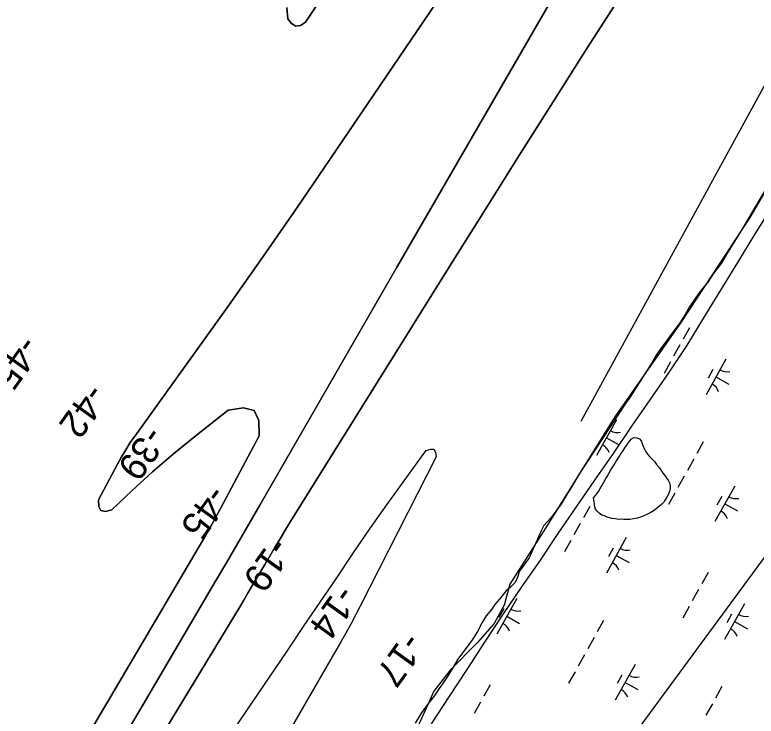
# Model space of a CAD drawing. Extents: x 3923531 to 3943530, y 207391 to 229799.
# Drawn here: x 3936304 to 3937214, y 219001 to 219861 of the extents above; entities that cross this region are included whole.
import ezdxf

# ---------------------------------------------------------------- set-up
doc = ezdxf.new("R2010")
doc.units = 0
for name, color, linetype in [('V-RIVR-EDGE', 7, 'Continuous'), ('V-RIVR-RANG', 7, 'Continuous'), ('V-RRAP-FSHR', 7, 'Continuous'), ('V-TOPO-DPTH', 7, 'Continuous'), ('V-TOPO-MINR', 7, 'Continuous'), ('V-TOPO-SHOR', 7, 'Continuous'), ('V-UTIL-LINE', 7, 'Continuous'), ('V-WETL-SWMP', 7, 'Continuous')]:
    doc.layers.add(name, color=color, linetype=linetype)

msp = doc.modelspace()

# ---------------------------------------------------------------- linework, layer by layer
at = {"layer": 'V-RIVR-EDGE'}
msp.add_lwpolyline([(3937264.42, 219712.49), (3937206.12, 219612.81), (3937121.31, 219483.62), (3937040.42, 219367.91), (3936955.04, 219231.41), (3936911.23, 219162.89), (3936904.49, 219137.05), (3936892.13, 219114.58), (3936871.91, 219090.99), (3936838.21, 219057.29), (3936817.99, 219031.45), (3936801.14, 218994.38), (3936792.15, 218976.4), (3936756.2, 218928.09), (3936705.65, 218856.2), (3936661.83, 218800.03), (3936627.01, 218753.97), (3936580.95, 218730.38), (3936545, 218713.52), (3936503.43, 218703.41), (3936484.84, 218694.49)], dxfattribs=at)
at = {"layer": 'V-RRAP-FSHR'}
msp.add_lwpolyline([(3936815.22, 218991.23), (3936837.11, 219024.71), (3936859.2, 219058.18), (3936880.89, 219091.66), (3936902.79, 219125.14), (3936925.4, 219158.13), (3936948.35, 219191.11), (3936970.67, 219224.9), (3936993.31, 219257.68), (3937015.94, 219290.47), (3937038.58, 219323.26), (3937061.21, 219356.5), (3937083.85, 219388.98), (3937106.48, 219421.96), (3937128.55, 219455.31), (3937149.45, 219489.41), (3937170.35, 219523.52), (3937191.24, 219557.63), (3937212.14, 219591.74), (3937233.37, 219625.84)], dxfattribs=at)
at = {"layer": 'V-TOPO-DPTH'}
for points in [[(3936839.17, 220119.81), (3936660.7, 219852.39), (3936654.31, 219848.4), (3936648.49, 219847.28), (3936643.49, 219850.48), (3936639.04, 219856.55), (3936637.46, 219870.32)], [(3936637.46, 219870.32), (3936639.04, 219856.55), (3936643.49, 219850.48), (3936648.49, 219847.28), (3936654.31, 219848.4), (3936660.7, 219852.39), (3936839.17, 220119.81)], [(3936125.75, 218524.05), (3936538.21, 219223.04), (3936541.92, 219229.42), (3936545.58, 219235.84), (3936549.15, 219242.31), (3936552.66, 219248.8), (3936603.69, 219344.79), (3936603.2, 219363.48), (3936597.58, 219376), (3936584.24, 219379.29), (3936565.77, 219376.43), (3936524.78, 219344.02), (3936498.45, 219322.49), (3936472.62, 219300.4), (3936447.53, 219277.46), (3936422.95, 219253.95), (3936415.13, 219252.06), (3936409.41, 219253.01), (3936406.86, 219258.21), (3936406.43, 219266.24), (3936429.59, 219309.92), (3936434.61, 219318.93), (3936439.87, 219327.78), (3936445.48, 219336.42), (3936451.34, 219344.91), (3936524.41, 219446.28), (3936566.72, 219505.52), (3936608.69, 219564.99), (3936650.15, 219624.83), (3936691.26, 219684.91), (3936943.66, 220057.15)], [(3936943.66, 220057.15), (3936691.26, 219684.91), (3936650.15, 219624.83), (3936608.69, 219564.99), (3936566.72, 219505.52), (3936524.41, 219446.28), (3936451.34, 219344.91), (3936445.48, 219336.42), (3936439.87, 219327.78), (3936434.61, 219318.93), (3936429.59, 219309.92), (3936406.43, 219266.24), (3936406.86, 219258.21), (3936409.41, 219253.01), (3936415.13, 219252.06), (3936422.95, 219253.95), (3936447.53, 219277.46), (3936472.62, 219300.4), (3936498.45, 219322.49), (3936524.78, 219344.02), (3936565.77, 219376.43), (3936584.24, 219379.29), (3936597.58, 219376), (3936603.2, 219363.48), (3936603.69, 219344.79), (3936552.66, 219248.8), (3936549.15, 219242.31), (3936545.58, 219235.84), (3936541.92, 219229.42), (3936538.21, 219223.04), (3936125.75, 218524.05)], [(3937073, 219924.42), (3937006.14, 219819.85), (3936964.69, 219754.77), (3936923.38, 219689.6), (3936882.28, 219624.3), (3936841.33, 219558.9), (3936647.39, 219248.06), (3936641.3, 219238.23), (3936635.26, 219228.36), (3936629.29, 219218.45), (3936623.37, 219208.51), (3936613.73, 219192.2), (3936612.67, 219190.39), (3936610.54, 219186.78), (3936609.48, 219184.98), (3936600.94, 219170.45), (3936595.58, 219161.39), (3936590.21, 219152.34), (3936584.79, 219143.32), (3936579.34, 219134.32), (3936150.31, 218428.2)], [(3936284.04, 218719.6), (3936343.8, 218817.63), (3936402.8, 218916.13), (3936461.3, 219014.93), (3936550.25, 219166.53), (3936563.86, 219189.78), (3936577.43, 219213.05), (3936590.95, 219236.35), (3936604.43, 219259.66), (3936772.41, 219550.86), (3936818.95, 219631.46), (3936865.54, 219712.04), (3936912.19, 219792.58), (3936958.89, 219873.09)], [(3936958.89, 219873.09), (3936912.19, 219792.58), (3936865.54, 219712.04), (3936818.95, 219631.46), (3936772.41, 219550.86), (3936604.43, 219259.66), (3936590.95, 219236.35), (3936577.43, 219213.05), (3936563.86, 219189.78), (3936550.25, 219166.53), (3936461.3, 219014.93), (3936402.8, 218916.13), (3936343.8, 218817.63), (3936284.04, 218719.6)]]:
    msp.add_lwpolyline(points, dxfattribs=at)
at = {"layer": 'V-TOPO-MINR'}
for points in [[(3936998.93, 219362.63), (3937298.09, 219910.54), (3937299.4, 219913.05), (3937300.67, 219915.58), (3937301.85, 219918.14), (3937302.99, 219920.73), (3937323.72, 219970.21), (3937335.15, 219997.57), (3937346.53, 220024.96), (3937357.84, 220052.37), (3937369.1, 220079.8), (3937639.89, 220741.77), (3937648.76, 220763.09), (3937657.81, 220784.33), (3937667.11, 220805.45), (3937676.59, 220826.5), (3937934.29, 221389.52)], [(3936839.17, 220119.81), (3936660.7, 219852.39), (3936654.31, 219848.4), (3936648.49, 219847.28), (3936643.49, 219850.48), (3936639.04, 219856.55), (3936637.46, 219870.32)], [(3936125.75, 218524.05), (3936538.21, 219223.04), (3936541.92, 219229.42), (3936545.58, 219235.84), (3936549.15, 219242.31), (3936552.66, 219248.8), (3936603.69, 219344.79), (3936603.2, 219363.48), (3936597.58, 219376), (3936584.24, 219379.29), (3936565.77, 219376.43), (3936524.78, 219344.02), (3936498.45, 219322.49), (3936472.62, 219300.4), (3936447.53, 219277.46), (3936422.95, 219253.95), (3936415.13, 219252.06), (3936409.41, 219253.01), (3936406.86, 219258.21), (3936406.43, 219266.24), (3936429.59, 219309.92), (3936434.61, 219318.93), (3936439.87, 219327.78), (3936445.48, 219336.42), (3936451.34, 219344.91), (3936524.41, 219446.28), (3936566.72, 219505.52), (3936608.69, 219564.99), (3936650.15, 219624.83), (3936691.26, 219684.91), (3936943.66, 220057.15)], [(3936150.31, 218428.2), (3936579.34, 219134.32), (3936584.79, 219143.32), (3936590.21, 219152.34), (3936595.58, 219161.39), (3936600.94, 219170.45), (3936609.48, 219184.98), (3936610.54, 219186.78), (3936612.67, 219190.39), (3936613.73, 219192.2), (3936623.37, 219208.51), (3936629.29, 219218.45), (3936635.26, 219228.36), (3936641.3, 219238.23), (3936647.39, 219248.06), (3936841.33, 219558.9), (3936882.28, 219624.3), (3936923.38, 219689.6), (3936964.69, 219754.77), (3937006.14, 219819.85), (3937073, 219924.42)], [(3936284.04, 218719.6), (3936343.8, 218817.63), (3936402.8, 218916.13), (3936461.3, 219014.93), (3936550.25, 219166.53), (3936563.86, 219189.78), (3936577.43, 219213.05), (3936590.95, 219236.35), (3936604.43, 219259.66), (3936772.41, 219550.86), (3936818.95, 219631.46), (3936865.54, 219712.04), (3936912.19, 219792.58), (3936958.89, 219873.09)], [(3936290.41, 218549.02), (3936331.52, 218620.72), (3936375.11, 218690.94), (3936420.36, 218760.18), (3936637.9, 219080.65), (3936658.25, 219110.64), (3936678.58, 219140.64), (3936698.9, 219170.65), (3936719.2, 219200.66), (3936739.7, 219230.54), (3936760.47, 219260.23), (3936781.65, 219289.62), (3936803.1, 219318.83), (3936808.89, 219326.58), (3936814.25, 219328.57), (3936818.25, 219328.36), (3936820.21, 219324.87), (3936820.82, 219319.19), (3936727.75, 219135.63), (3936722.04, 219124.6), (3936716.22, 219113.64), (3936710.21, 219102.77), (3936704.09, 219091.97), (3936365.07, 218505.33)]]:
    msp.add_lwpolyline(points, dxfattribs=at)
at = {"layer": 'V-TOPO-SHOR'}
msp.add_lwpolyline([(3937014.24, 219268.6), (3937016.24, 219270.95), (3937018.25, 219273.51), (3937020.25, 219276.25), (3937022.27, 219280.19), (3937024.28, 219283.53), (3937026.7, 219288.06), (3937029.12, 219292.38), (3937030.73, 219294.94), (3937032.95, 219298.68), (3937035.56, 219303), (3937037.78, 219306.74), (3937039.58, 219309.29), (3937041.6, 219313.03), (3937044.01, 219316.37), (3937046.03, 219319.9), (3937047.64, 219322.86), (3937050.04, 219326), (3937052.66, 219329.93), (3937055.07, 219333.46), (3937056.68, 219336.02), (3937058.88, 219338.77), (3937060.88, 219341.12), (3937063.67, 219342.67), (3937067.43, 219342.43), (3937070.58, 219341.02), (3937072.73, 219338.62), (3937074.08, 219335.44), (3937075.03, 219332.07), (3937076.78, 219328.49), (3937078.53, 219325.31), (3937080.67, 219321.92), (3937083.01, 219319.32), (3937085.56, 219316.73), (3937088.88, 219313.13), (3937091.62, 219309.74), (3937094.75, 219305.95), (3937097.08, 219302.17), (3937099.22, 219298.98), (3937101.57, 219295.99), (3937103.71, 219292.8), (3937105.86, 219290.21), (3937107.41, 219287.02), (3937108.17, 219283.85), (3937108.33, 219280.49), (3937107.5, 219276.54), (3937106.08, 219273.19), (3937104.26, 219269.65), (3937102.25, 219266.3), (3937100.64, 219263.55), (3937098.24, 219261), (3937095.24, 219258.27), (3937091.25, 219255.34), (3937088.46, 219252.99), (3937084.68, 219250.66), (3937080.5, 219248.72), (3937075.93, 219246.6), (3937071.96, 219244.86), (3937067.79, 219243.71), (3937063.43, 219242.97), (3937058.87, 219242.22), (3937055.51, 219242.06), (3937051.55, 219242.1), (3937048.39, 219242.33), (3937044.43, 219242.17), (3937041.27, 219242.8), (3937037.12, 219243.44), (3937033.96, 219244.26), (3937030.81, 219245.08), (3937027.46, 219246.5), (3937024.5, 219247.52), (3937021.16, 219249.73), (3937018.62, 219252.14), (3937016.67, 219254.73), (3937015.91, 219257.7), (3937015.54, 219260.87), (3937014.78, 219264.05), (3937014.24, 219268.6)], dxfattribs=at)
at = {"layer": 'V-UTIL-LINE'}
msp.add_lwpolyline([(3939084.62, 223621.72), (3938057.71, 221140.48), (3938136.4, 220832.47), (3937591.63, 219695.21), (3936312.73, 217957.68), (3935106.6, 216231.89), (3934055.84, 214955.86), (3930691.13, 211497.88), (3930457.99, 211185.48)], dxfattribs=at)
at = {"layer": 'V-WETL-SWMP'}
for p, q in [((3937225.89, 219647.62), (3937197.08, 219599.08)), ((3937197.08, 219599.08), (3937179.04, 219570.16)), ((3937179.04, 219570.16), (3937170.72, 219556.29)), ((3937170.72, 219556.29), (3937162.03, 219544.62)), ((3937168.11, 219552.79), (3937168.2, 219552.74)), ((3937162.03, 219544.62), (3937154.34, 219533.34)), ((3937154.34, 219533.34), (3937146.46, 219523.65)), ((3937146.46, 219523.65), (3937139.59, 219514.55)), ((3937139.59, 219514.55), (3937131.9, 219502.87)), ((3937131.9, 219502.87), (3937126.62, 219493.56)), ((3937126.62, 219493.56), (3937119.12, 219482.07)), ((3937119.12, 219482.07), (3937111.64, 219471.98)), ((3937132.01, 219477.28), (3937124.21, 219463.31)), ((3937111.64, 219471.98), (3937104.97, 219462.88)), ((3937104.97, 219462.88), (3937096.88, 219452)), ((3937120.31, 219456.32), (3937112.5, 219442.36)), ((3937096.88, 219452), (3937091.02, 219443.69)), ((3937091.02, 219443.69), (3937085.33, 219433.58)), ((3937176.69, 219438.91), (3937152.31, 219395.26)), ((3937085.33, 219433.58), (3937077.02, 219420.71)), ((3937108.6, 219435.37), (3937100.8, 219421.4)), ((3937077.02, 219420.71), (3937058.58, 219391.99)), ((3937160.69, 219426.09), (3937154.84, 219415.61)), ((3937164.5, 219417.08), (3937180.21, 219408.31)), ((3937054.33, 219385.66), (3936996.01, 219297.36)), ((3937058.58, 219391.99), (3937054.33, 219385.66)), ((3937042.29, 219364.26), (3937017.9, 219320.61)), ((3937030.09, 219342.44), (3937045.81, 219333.66)), ((3937056.68, 219336.02), (3937058.88, 219338.76)), ((3937058.88, 219338.76), (3937060.88, 219341.12)), ((3937060.88, 219341.12), (3937063.67, 219342.67)), ((3937063.67, 219342.67), (3937067.43, 219342.43)), ((3937067.43, 219342.43), (3937070.58, 219341.02)), ((3937070.58, 219341.02), (3937072.73, 219338.62)), ((3937072.73, 219338.62), (3937074.08, 219335.44)), ((3937050.04, 219326), (3937052.66, 219329.93)), ((3937052.66, 219329.93), (3937055.07, 219333.46)), ((3937055.07, 219333.46), (3937056.68, 219336.02)), ((3937074.08, 219335.44), (3937075.03, 219332.07)), ((3937075.03, 219332.07), (3937076.78, 219328.49)), ((3937148.95, 219337.23), (3937141.15, 219323.26)), ((3937044.01, 219316.36), (3937046.02, 219319.9)), ((3937046.02, 219319.9), (3937047.64, 219322.86)), ((3937047.64, 219322.86), (3937050.04, 219326)), ((3937076.78, 219328.49), (3937078.52, 219325.31)), ((3937078.52, 219325.31), (3937080.67, 219321.92)), ((3937080.67, 219321.92), (3937083.01, 219319.32)), ((3937039.58, 219309.29), (3937041.6, 219313.03)), ((3937041.6, 219313.03), (3937044.01, 219316.36)), ((3937083.01, 219319.32), (3937085.56, 219316.73)), ((3937085.56, 219316.73), (3937088.88, 219313.13)), ((3937088.88, 219313.13), (3937091.62, 219309.74)), ((3937137.24, 219316.28), (3937129.44, 219302.31)), ((3937032.95, 219298.68), (3937035.56, 219303)), ((3937035.56, 219303), (3937037.78, 219306.74)), ((3937037.78, 219306.74), (3937039.58, 219309.29)), ((3937091.62, 219309.74), (3937094.75, 219305.95)), ((3937094.75, 219305.95), (3937097.08, 219302.17)), ((3937097.08, 219302.17), (3937099.22, 219298.98)), ((3936996.01, 219297.36), (3936987.68, 219282.69)), ((3937029.12, 219292.38), (3937030.73, 219294.94)), ((3937030.73, 219294.94), (3937032.95, 219298.68)), ((3937099.22, 219298.98), (3937101.57, 219295.99)), ((3937101.57, 219295.99), (3937103.71, 219292.8)), ((3937103.71, 219292.8), (3937105.86, 219290.21)), ((3937125.54, 219295.33), (3937117.74, 219281.36)), ((3937022.27, 219280.19), (3937024.28, 219283.53)), ((3937024.28, 219283.53), (3937026.7, 219288.06)), ((3937026.7, 219288.06), (3937029.12, 219292.38)), ((3937105.86, 219290.21), (3937107.41, 219287.02)), ((3937107.41, 219287.02), (3937108.17, 219283.85)), ((3937108.17, 219283.85), (3937108.33, 219280.49)), ((3936987.68, 219282.69), (3936981.4, 219272.79)), ((3937018.25, 219273.51), (3937020.25, 219276.25)), ((3937020.25, 219276.25), (3937022.27, 219280.19)), ((3937113.83, 219274.37), (3937106.03, 219260.41)), ((3937107.5, 219276.54), (3937106.08, 219273.19)), ((3937108.33, 219280.49), (3937107.5, 219276.54)), ((3937187.5, 219283.14), (3937163.11, 219239.49)), ((3936981.4, 219272.79), (3936974.5, 219260.9)), ((3937014.24, 219268.6), (3937016.24, 219270.95)), ((3937014.78, 219264.05), (3937014.24, 219268.6)), ((3937016.24, 219270.95), (3937018.25, 219273.51)), ((3937102.25, 219266.3), (3937100.64, 219263.55)), ((3937104.26, 219269.65), (3937102.25, 219266.3)), ((3937106.08, 219273.19), (3937104.26, 219269.65)), ((3937171.5, 219270.31), (3937165.64, 219259.84)), ((3936974.5, 219260.9), (3936961.77, 219244.28)), ((3937009.62, 219258.19), (3937001.82, 219244.22)), ((3937015.54, 219260.87), (3937014.78, 219264.05)), ((3937015.91, 219257.7), (3937015.54, 219260.87)), ((3937016.67, 219254.73), (3937015.91, 219257.7)), ((3937095.24, 219258.27), (3937091.25, 219255.34)), ((3937098.24, 219261.01), (3937095.24, 219258.27)), ((3937100.64, 219263.55), (3937098.24, 219261.01)), ((3937175.31, 219261.31), (3937191.02, 219252.53)), ((3937018.62, 219252.14), (3937016.67, 219254.73)), ((3937021.16, 219249.73), (3937018.62, 219252.14)), ((3937024.5, 219247.52), (3937021.16, 219249.73)), ((3937027.46, 219246.5), (3937024.5, 219247.52)), ((3937080.5, 219248.72), (3937075.93, 219246.6)), ((3937084.68, 219250.66), (3937080.5, 219248.72)), ((3937088.46, 219252.99), (3937084.68, 219250.66)), ((3937091.25, 219255.34), (3937088.46, 219252.99)), ((3936961.77, 219244.28), (3936953.1, 219234.61)), ((3937030.81, 219245.08), (3937027.46, 219246.5)), ((3937037.12, 219243.44), (3937030.81, 219245.08)), ((3937041.27, 219242.8), (3937037.12, 219243.44)), ((3937044.43, 219242.17), (3937041.27, 219242.8)), ((3937048.39, 219242.33), (3937044.43, 219242.17)), ((3937051.55, 219242.1), (3937048.39, 219242.33)), ((3937055.51, 219242.06), (3937051.55, 219242.1)), ((3937058.87, 219242.22), (3937055.51, 219242.06)), ((3937063.43, 219242.97), (3937058.87, 219242.22)), ((3937067.79, 219243.71), (3937063.43, 219242.97)), ((3937071.96, 219244.86), (3937067.79, 219243.71)), ((3937075.93, 219246.6), (3937071.96, 219244.86)), ((3936953.1, 219234.61), (3936950.04, 219228.26)), ((3936997.92, 219237.24), (3936990.11, 219223.27)), ((3936950.04, 219228.26), (3936935.14, 219194.92)), ((3937054.3, 219219.83), (3937029.91, 219176.18)), ((3936986.21, 219216.29), (3936978.41, 219202.32)), ((3937038.3, 219207), (3937032.44, 219196.53)), ((3936935.14, 219194.92), (3936923.01, 219178.1)), ((3937042.11, 219198), (3937057.82, 219189.22)), ((3936923.01, 219178.1), (3936921.15, 219172.34)), ((3937154.83, 219177.07), (3937147.03, 219163.1)), ((3936918.09, 219165), (3936912.85, 219159.47)), ((3936921.15, 219172.34), (3936918.09, 219165)), ((3936912.85, 219159.47), (3936906.61, 219154.35)), ((3937143.13, 219156.12), (3937135.33, 219142.15)), ((3936906.61, 219154.35), (3936898.54, 219144.27)), ((3936892.89, 219137.75), (3936889.24, 219132.2)), ((3936898.54, 219144.27), (3936892.89, 219137.75)), ((3936919.89, 219145.18), (3936895.51, 219101.53)), ((3937199.51, 219138.7), (3937175.13, 219095.05)), ((3936889.24, 219132.2), (3936882.38, 219124.1)), ((3936903.89, 219132.35), (3936898.04, 219121.88)), ((3937131.42, 219135.16), (3937123.62, 219121.19)), ((3936882.38, 219124.1), (3936877.51, 219115.58)), ((3936907.7, 219123.35), (3936923.41, 219114.57)), ((3937183.51, 219125.88), (3937177.66, 219115.4)), ((3936877.51, 219115.58), (3936871.81, 219104.87)), ((3937026.56, 219118.15), (3937018.75, 219104.18)), ((3937187.32, 219116.88), (3937203.03, 219108.1)), ((3936871.81, 219104.87), (3936864.72, 219093.59)), ((3936864.72, 219093.59), (3936857.04, 219083.5)), ((3937014.85, 219097.19), (3937007.05, 219083.23)), ((3936857.04, 219083.5), (3936847.74, 219070.64)), ((3937003.15, 219076.24), (3936995.34, 219062.27)), ((3936847.74, 219070.64), (3936840.64, 219058.95)), ((3936840.64, 219058.95), (3936833.34, 219047.06)), ((3937065.11, 219064.05), (3937040.72, 219020.4)), ((3936833.34, 219047.06), (3936824.03, 219033.6)), ((3936991.44, 219055.29), (3936983.64, 219041.32)), ((3937049.1, 219051.23), (3937043.25, 219040.75)), ((3936887.23, 219039.11), (3936879.42, 219025.14)), ((3937052.91, 219042.23), (3937068.63, 219033.45)), ((3936824.03, 219033.6), (3936817.96, 219024.9)), ((3937171.77, 219037.02), (3937163.97, 219023.05)), ((3936817.96, 219024.9), (3936808.67, 219013.03)), ((3936808.67, 219013.03), (3936801.99, 219003.53)), ((3936875.52, 219018.16), (3936867.72, 219004.19)), ((3937160.07, 219016.07), (3937152.26, 219002.1)), ((3936801.99, 219003.53), (3936795.29, 218992.24))]:
    msp.add_line(p, q, dxfattribs=at)
for centre, start, end in [((3937178.18, 219441.08), 240.03808, 281.58174), ((3937151.23, 219392.86), 20.03808, 61.58174), ((3937043.77, 219366.44), 240.03808, 281.58174), ((3937016.83, 219318.21), 20.03808, 61.58174), ((3937188.98, 219285.31), 240.03808, 281.58174), ((3937162.04, 219237.08), 20.03808, 61.58174), ((3937055.78, 219222), 240.03808, 281.58174), ((3937028.84, 219173.77), 20.03808, 61.58174), ((3936921.38, 219147.35), 240.03808, 281.58174), ((3937201, 219140.87), 240.03808, 281.58174), ((3936894.44, 219099.12), 20.03808, 61.58174), ((3937174.06, 219092.65), 20.03808, 61.58174), ((3937066.59, 219066.23), 240.03808, 281.58174), ((3937039.65, 219018), 20.03808, 61.58174)]:
    msp.add_arc(centre, 17.62, start, end, dxfattribs=at)

# ---------------------------------------------------------------- texts
at = {"layer": 'V-RIVR-RANG'}
for s, rotation, p in [('-45', 234.3985, (3936311.97, 219470.03)), ('-42', 234.3985, (3936394.03, 219410.98)), ('-39', 234.3985, (3936466.14, 219359)), ('-45', 234.25833, (3936543.45, 219286.58)), ('-19', 234.25833, (3936620.22, 219222.05)), ('-14', 234.25833, (3936701.52, 219163.84)), ('-17', 234.25833, (3936782.91, 219105.73))]:
    msp.add_text(s, height=33.5, rotation=rotation, dxfattribs=at).set_placement(p)

doc.saveas('drawing.dxf')
